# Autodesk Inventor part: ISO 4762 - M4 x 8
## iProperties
IsCustomPart: 0
Created: 2007-11
Part Number: ISO 4762 - M4 x 8
Material: Stainless Steel, 440C
Description: Hexagon Socket Head Cap Screw
Document SubType Name: Modeling
Standard: ISO 4762
Designer: CM
Standard Revision: Fourth edition 2004-03-01
Standards Organization: ISO
Language: en-US
Size Designation: M4 x 8
Categories: <MemberInstance><Categories><Category DisplayName="Fasteners" InternalName="e4da775c-781d-43d5-af7c-5136215cf5a6" Mnemonic="FSTN"><Category DisplayName="Bolts"
Density: 7.75 g/cm^3
Mass: 1.81382 g
Surface Area: 2.80588 cm^2
Volume: 0.234041 cm^3
Author: CM
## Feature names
1. Body [Revolution]
2. Slot [Extrusion]
3. Fillet1
4. Chamfer1
5. Fillet2
